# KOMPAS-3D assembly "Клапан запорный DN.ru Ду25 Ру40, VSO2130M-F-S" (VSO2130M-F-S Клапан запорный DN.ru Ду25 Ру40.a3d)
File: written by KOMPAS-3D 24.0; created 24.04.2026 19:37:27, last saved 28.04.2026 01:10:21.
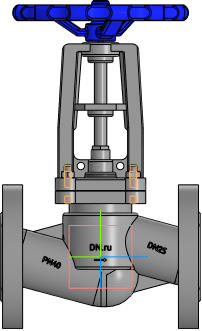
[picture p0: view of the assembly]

Document properties: Автор: DN.ru; Полное имя файла: C:\Работа\ГОТОВЫЕ ИСХОДНИКИ\VSO2130M-F-S Клапан запорный сильфонный DN.ru Ду15-100 Ру40\исходные материалы\DN25\VSO2130M-F-S Клапан запорный DN.ru Ду25 Ру40.a3d

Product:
- Component [detail]: Корпус  | qty 1  | pos. 1  | Масса: 6.9; Автор: R2D2; source file: Korpus.m3d
- Component [detail]: Деталь  | qty 1  | pos. 2  | Масса: 1.121165; Автор: mrdid; source file: rama.m3d
- Component [detail]: Деталь2  | qty 1  | pos. 3  | Масса: 0.594157; Автор: R2D2; additional columns: Типовые; source file: shturval.m3d
- Component [standard]: Шпилька М6-6gx25 ГОСТ 22032-76  | qty 4  | Масса: 0.005789; Раздел спецификации: Стандартные изделия; Рассекать на разрезах: no
- Component [standard]: Гайка М6-6H ГОСТ 5915-70  | qty 4  | Масса: 0.002573; Раздел спецификации: Стандартные изделия; Рассекать на разрезах: no
- Part/product: Клапан запорный DN.ru Ду25 Ру40  | designation VSO2130M-F-S
    Масса: 6
    Раздел спецификации: Прочие изделия
    Примечание: D090-01972

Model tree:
1. Контекстная связь:1  (with: Эскиз:2, Ребро.Элемент выдавливания:14, Контекстная связь (Деталь):1)
2. Контекстная связь:2  (with: Контекстная связь (Деталь):2)
3. Массив по концентрической сетке:1  (with: Грань.Элемент выдавливания:1, Грань.Элемент выдавливания:15, Грань.Элемент выдавливания:3, Грань.Элемент выдавливания:2, Грань.Элемент выдавливания:16, Грань.Элемент выдавливания:17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)  (labels: Грань.Твердое тело1)  (4 pattern instances)
     Шаг 2 = 360; Угол = 8

Referenced files in C:\Работа\ГОТОВЫЕ ИСХОДНИКИ\VSO2130M-F-S Клапан запорный сильфонный DN.ru Ду15-100 Ру40\исходные материалы\DN25\: Korpus.m3d, rama.m3d, shturval.m3d
Referenced files in C:\Program Files\ASCON\KOMPAS-3D v24\Libs\PolynomLib\DATA\vault\Methods\Kompas\3D\: PLib_Stud_1_900.m3d, PLib_Nut_OST92_900.m3d
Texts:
  BOSimple***PART:e489ae6d-d315-b2e9-dd59-4407119351be***SHORTLOC:Root±30±20±10±120±10±20[Нет;Без покрытия;Без указания материала;-;6;25;1;1]
  Крепежное изделие ГОСТ
  BOSimple***PART:832b7c99-94b5-75d7-382c-73b3a2f1c6df***SHORTLOC:Root±30±10±20±©{}110±10±50±60[Нет;Без покрытия;Без указания материала;-;6;1;10]
  Программные изделия  и базы данных
  VSO2130M-F-S
  Деталь2 Деталь2
  Шпилька М6-6gx25 ГОСТ 22032-76 (1)
  cut1
  Гайка М6-6H ГОСТ 5915-70 (1)
  bcut1
  hole1
  hcut1
  hole2
  Шпилька М6-6gx25 ГОСТ 22032-76 (2)
  Гайка М6-6H ГОСТ 5915-70 (2)
  Шпилька М6-6gx25 ГОСТ 22032-76 (3)
  Гайка М6-6H ГОСТ 5915-70 (3)
  Шпилька М6-6gx25 ГОСТ 22032-76 (4)
  Гайка М6-6H ГОСТ 5915-70 (4)
  Plane. Начало координат
  Плоскость XY.Начало координат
